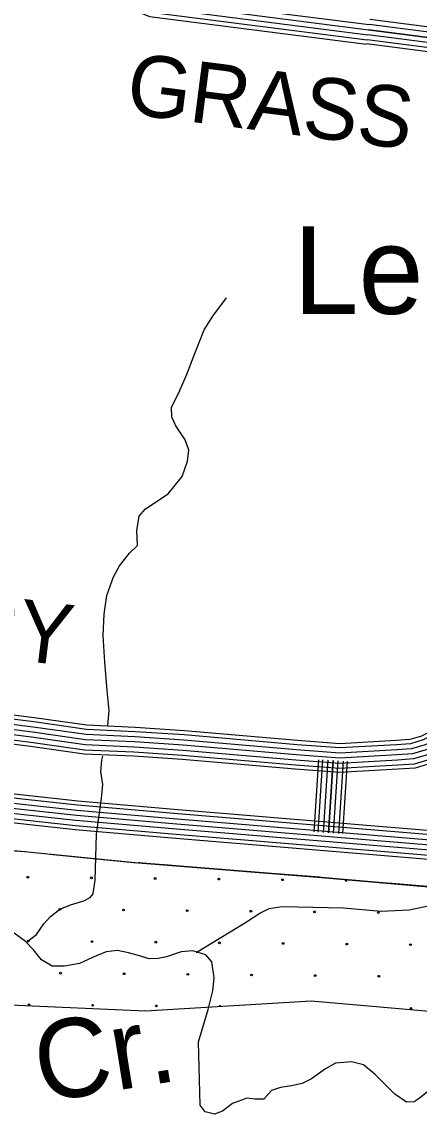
# Model space of a CAD drawing. Extents: x 1788175 to 1969470, y 584502 to 738744.
# Drawn here: x 1839858 to 1842257, y 674647 to 681239 of the extents above; entities that cross this region are included whole.
import ezdxf

# ---------------------------------------------------------------- set-up
doc = ezdxf.new("R2010")
doc.units = 0
for name, color, linetype in [('DESIGN - DRAINAGE - Bridges and Cross Drains Size Text', 7, 'Continuous'), ('DESIGN - EROSION CONTROL - Devices', 7, 'Continuous'), ('DESIGN - ROW - Right-of-Way and Easement Labels', 7, 'Continuous'), ('DESIGN - SCRATCH - User 1', 7, 'Continuous'), ('DESIGN - TRANSPORTATION - Text', 7, 'Continuous'), ('SURVEY - CONTOURS - Index with Text', 7, 'Continuous'), ('SURVEY - TRANSPORTATION - Roads', 7, 'Continuous'), ('SURVEY - VEGETATION - Features with Text', 7, 'Continuous')]:
    doc.layers.add(name, color=color, linetype=linetype)

msp = doc.modelspace()

# ---------------------------------------------------------------- linework, layer by layer
at = {"layer": 'DESIGN - EROSION CONTROL - Devices'}
for centre in [(1839893.4, 676076.8), (1840277.9, 676073.1), (1840662.5, 676069.4), (1841047, 676065.6), (1841431.6, 676061.9), (1840087.5, 675882.7), (1840472.1, 675878.9), (1840856.6, 675875.2), (1841241.2, 675871.5), (1841625.7, 675867.7), (1842010.3, 675864), (1839897.1, 675692.3), (1840281.6, 675688.5), (1840666.2, 675684.8), (1841050.8, 675681.1), (1841435.3, 675677.3), (1841819.9, 675673.6), (1842204.4, 675669.9), (1840091.2, 675498.1), (1840475.8, 675494.4), (1840860.3, 675490.7), (1841244.9, 675486.9), (1841629.4, 675483.2), (1842014, 675479.5), (1839900.8, 675307.7), (1840285.4, 675304), (1840669.9, 675300.3), (1842208.1, 675285.3)]:
    msp.add_circle(centre, 5.28, dxfattribs=at)
for centre, start, end in [((1841816.1, 676058.2), 108.99148, 61.08008), ((1841054.5, 675296.5), 357.64403, 189.12838)]:
    msp.add_arc(centre, 5.28, start, end, dxfattribs=at)
at = {"layer": 'DESIGN - SCRATCH - User 1'}
for points in [[(1839619, 676249.9), (1839873.1, 676232.3), (1840562.4, 676163.7)], [(1840562.4, 676163.7), (1841666.8, 676076), (1842869.2, 675971.5), (1843035.1, 675956.1), (1843451.8, 675929), (1843737.3, 675929), (1843984.3, 675940.6), (1844358.5, 675990.8)], [(1844232.2, 675412.9), (1844051.8, 675193), (1843754.9, 675179.1), (1843427.5, 675179.1), (1842976, 675208.3), (1842801.9, 675224.6), (1841604.7, 675328.5), (1840603.9, 675269.3)], [(1840603.9, 675269.3), (1839785.1, 675304.6), (1839793.9, 674996.2), (1839617.8, 674969.8), (1839019.1, 675031.5), (1838807.8, 674855.2), (1838519.3, 674844.9), (1838260.6, 674867.8), (1838137.5, 674913.9), (1838183.1, 675227)]]:
    msp.add_lwpolyline(points, dxfattribs=at)
at = {"layer": 'DESIGN - TRANSPORTATION - Text'}
for points in [[(1840377.5, 676990.9), (1840385.6, 677083.1), (1840373.5, 677203.4), (1840358.2, 677375.8), (1840348.8, 677536), (1840354.8, 677664), (1840370.6, 677777.9), (1840410.3, 677889.3), (1840447.4, 677956.8), (1840508.5, 678031.9), (1840555.2, 678079.2), (1840552.6, 678169.3), (1840565.9, 678255.2), (1840604.6, 678300.6), (1840741.9, 678390.5), (1840825.4, 678495.2), (1840858.9, 678588.8), (1840865.9, 678654.7), (1840844.9, 678717.1), (1840788.3, 678802.1), (1840763.2, 678852.5), (1840762.2, 678914.6), (1840801.3, 678992), (1840853.1, 679107.3), (1840898.9, 679226.7), (1840959.3, 679379.8), (1841010.6, 679463.1), (1841094.2, 679573.8)], [(1839885, 675685.2), (1839946.6, 675731), (1839989.6, 675796.3), (1840030.3, 675839.7), (1840086.9, 675884.9), (1840151.2, 675909.8), (1840231.5, 675934.6), (1840269.8, 675954), (1840288.1, 675977.7), (1840301.4, 676059.6), (1840307.8, 676337.7), (1840339.2, 676551.4), (1840346.5, 676637.3), (1840333.8, 676713.6), (1840340.9, 676783.5), (1840346.5, 676808.4)], [(1840911, 675623.4), (1841209.1, 675803.6), (1841295.9, 675860.2), (1841352.2, 675887.4), (1841430.3, 675900.1), (1841799.8, 675892.2), (1842027.2, 675872.6), (1842197.1, 675879.9), (1842321.3, 675905.9), (1842397.8, 675942.7), (1842434.4, 675986.2), (1842630, 676186.4)], [(1840924, 675082.7), (1840982.3, 675278.1), (1841011.7, 675391.9), (1841018.7, 675469.8), (1841005.9, 675566.1), (1840968.5, 675608.6), (1840890.9, 675633.5), (1840820.9, 675626.4), (1840730.6, 675597.5), (1840680.5, 675586.1), (1840626.6, 675584.7), (1840554.9, 675605.6), (1840501.1, 675620.3), (1840435.4, 675635.1), (1840367.3, 675625.9), (1840285, 675592.9), (1840206.6, 675555.8), (1840114.6, 675540.9), (1840040.6, 675539.8), (1839977.2, 675578.6), (1839928, 675639.2), (1839880.7, 675689.9), (1839811.3, 675738.7)], [(1842328.9, 674799.3), (1842256.3, 674742.2), (1842226.1, 674720.5), (1842180.1, 674719.1), (1842110.8, 674768), (1841992.4, 674885.5), (1841921.2, 674944.4), (1841849.5, 674963.3), (1841751.5, 674954.5), (1841691.1, 674921.2), (1841606.5, 674860.2), (1841550.2, 674832.8), (1841486.1, 674817.6), (1841420, 674808.4), (1841365.8, 674789), (1841319.2, 674737.5), (1841265.3, 674738.2), (1841217.4, 674742.8), (1841129.1, 674711.8), (1841068.6, 674664.5), (1841020.4, 674647.1), (1840964.7, 674661.8), (1840935.2, 674702.2), (1840924, 675082.7)]]:
    msp.add_lwpolyline(points, dxfattribs=at)
at = {"layer": 'SURVEY - CONTOURS - Index with Text'}
for points in [[(1846534.1, 676635), (1846352.5, 676635), (1846238.5, 676620.8), (1845873.8, 676586.3), (1845636.2, 676551.8), (1845548.2, 676546), (1845443.4, 676528.2), (1845167.8, 676467.4), (1844844.8, 676410.5), (1844348.9, 676328.4), (1844070.1, 676286), (1843940.6, 676275.5), (1843822.6, 676265.1), (1843687, 676265.1), (1843472.1, 676265.1), (1843224.8, 676282.8), (1843014.6, 676297), (1842328.9, 676357.8), (1840777.3, 676486.6), (1840195.7, 676536.6), (1838791.7, 676690.3)], [(1846532.2, 676578.3), (1846356, 676578.3), (1846244.7, 676564.4), (1845880.5, 676530), (1845642.2, 676495.4), (1845554.8, 676489.6), (1845454.2, 676472.5), (1845178.9, 676411.7), (1844854.4, 676354.6), (1844357.8, 676272.4), (1844076.7, 676229.6), (1843945.4, 676219), (1843825.1, 676208.4), (1843687, 676208.4), (1843470.1, 676208.4), (1843220.9, 676226.2), (1843010.2, 676240.5), (1842324.1, 676301.3), (1840772.5, 676430.1), (1840190.2, 676480.1), (1838785.6, 676634)], [(1846533.2, 676609.3), (1846354.1, 676609.3), (1846241.3, 676595.2), (1845876.9, 676560.8), (1845638.9, 676526.2), (1845551.2, 676520.4), (1845448.3, 676503), (1845172.8, 676442.1), (1844849.1, 676385.2), (1844353, 676303), (1844073.1, 676260.5), (1843942.8, 676249.9), (1843823.7, 676239.4), (1843687, 676239.4), (1843471.2, 676239.4), (1843223, 676257.1), (1843012.6, 676271.4), (1842326.7, 676332.2), (1840775.1, 676461), (1840193.2, 676511), (1838788.9, 676664.8)], [(1846530.2, 676516.3), (1846359.9, 676516.3), (1846251.5, 676502.7), (1845887.9, 676468.4), (1845648.7, 676433.7), (1845562.1, 676427.9), (1845466.1, 676411.7), (1845190.9, 676350.9), (1844864.8, 676293.5), (1844367.5, 676211.1), (1844083.8, 676168), (1843950.6, 676157.2), (1843827.8, 676146.4), (1843687, 676146.4), (1843467.8, 676146.4), (1843216.5, 676164.3), (1843005.4, 676178.7), (1842318.8, 676239.5), (1840767.3, 676368.3), (1840184.2, 676418.4), (1838778.9, 676572.3)], [(1846531.2, 676547.3), (1846357.9, 676547.3), (1846248.1, 676533.5), (1845884.2, 676499.2), (1845645.5, 676464.5), (1845558.5, 676458.7), (1845460.2, 676442.1), (1845184.9, 676381.3), (1844859.6, 676324.1), (1844362.7, 676241.8), (1844080.3, 676198.8), (1843948, 676188.1), (1843826.4, 676177.4), (1843687, 676177.4), (1843468.9, 676177.4), (1843218.7, 676195.3), (1843007.8, 676209.6), (1842321.4, 676270.4), (1840769.9, 676399.2), (1840187.2, 676449.3), (1838782.3, 676603.1)], [(1846531.2, 676547.3), (1846357.9, 676547.3), (1846248.1, 676533.5), (1845884.2, 676499.2), (1845645.5, 676464.5), (1845558.5, 676458.7), (1845460.2, 676442.1), (1845184.9, 676381.3), (1844859.6, 676324), (1844362.7, 676241.8), (1844080.3, 676198.8), (1843948, 676188.1), (1843826.4, 676177.4), (1843687, 676177.4), (1843468.9, 676177.4), (1843218.7, 676195.3), (1843007.8, 676209.6), (1842321.4, 676270.4), (1840769.9, 676399.2), (1840187.2, 676449.3), (1838782.3, 676603.1)], [(1846528.4, 676460.6), (1846363.3, 676460.6), (1846257.5, 676447.3), (1845894.5, 676413.1), (1845654.6, 676378.2), (1845568.6, 676372.5), (1845476.8, 676357), (1845201.8, 676296.2), (1844874.2, 676238.6), (1844376.3, 676156.1), (1844090.3, 676112.6), (1843955.3, 676101.7), (1843830.3, 676090.6), (1843687, 676090.6), (1843465.8, 676090.6), (1843212.7, 676108.7), (1843001, 676123.1), (1842314, 676184), (1840762.6, 676312.8), (1840178.8, 676363), (1838773, 676516.9)], [(1846529.2, 676485.3), (1846361.8, 676485.3), (1846254.9, 676471.9), (1845891.6, 676437.6), (1845652, 676402.8), (1845565.7, 676397.1), (1845472, 676381.2), (1845197, 676320.5), (1844870, 676262.9), (1844372.4, 676180.5), (1844087.4, 676137.2), (1843953.2, 676126.3), (1843829.2, 676115.4), (1843687, 676115.4), (1843466.7, 676115.4), (1843214.4, 676133.4), (1843003, 676147.7), (1842316.1, 676208.6), (1840764.7, 676337.4), (1840181.2, 676387.6), (1838775.6, 676541.5)]]:
    msp.add_lwpolyline(points, dxfattribs=at)
at = {"layer": 'SURVEY - TRANSPORTATION - Roads'}
for points in [[(1844246.8, 680947.7), (1844137.1, 681178.6), (1843846.7, 681752.4), (1843754.5, 681949.6), (1843711.3, 681999.1), (1843670.8, 682040.8), (1843614.1, 682076.5), (1843508.5, 682101.9), (1842138.8, 682301.2), (1840817, 682504.2), (1840751.3, 682505), (1840674.7, 682481.8), (1840611.1, 682404.1), (1840586.9, 682273.6), (1840522.4, 681458.4), (1840519.6, 681415.3), (1840523.4, 681313.6), (1840628.6, 681271.9), (1841940.1, 681104.6)], [(1844223.6, 680936.6), (1844114, 681167.3), (1843823.6, 681741.2), (1843732.7, 681935.4), (1843692.4, 681981.7), (1843654.5, 682020.7), (1843603.9, 682052.5), (1843503.6, 682076.6), (1842135, 682275.7), (1840814.8, 682478.5), (1840755, 682479.2), (1840689.7, 682459.4), (1840635.2, 682392.9), (1840612.4, 682270.2), (1840548.1, 681456.6), (1840545.3, 681415), (1840548.5, 681331.3), (1840635.1, 681297), (1841943.4, 681130.1)], [(1844195.5, 680923.3), (1844086.2, 681153.6), (1843795.7, 681727.6), (1843706.5, 681918.3), (1843669.6, 681960.7), (1843634.9, 681996.4), (1843591.7, 682023.5), (1843497.8, 682046.1), (1842130.4, 682245.1), (1840812.3, 682447.5), (1840759.4, 682448.2), (1840707.7, 682432.5), (1840664.2, 682379.4), (1840643.2, 682266.1), (1840579, 681454.4), (1840576.4, 681414.5), (1840578.7, 681352.7), (1840642.9, 681327.3), (1841947.3, 681160.9)], [(1844167.5, 680910), (1844058.4, 681140), (1843767.8, 681714), (1843680.3, 681901.3), (1843646.8, 681939.7), (1843615.2, 681972.1), (1843579.5, 681994.6), (1843491.9, 682015.6), (1842125.8, 682214.4), (1840809.7, 682416.6), (1840763.8, 682417.1), (1840725.7, 682405.6), (1840693.2, 682365.9), (1840673.9, 682262.1), (1840609.9, 681452.1), (1840607.4, 681414.1), (1840608.9, 681374.1), (1840650.7, 681357.5), (1841951.2, 681191.6)], [(1844167.5, 680910), (1844058.4, 681140), (1843767.8, 681714), (1843680.3, 681901.3), (1843646.8, 681939.7), (1843615.2, 681972.1), (1843579.5, 681994.6), (1843491.9, 682015.6), (1842125.8, 682214.4), (1840809.7, 682416.6), (1840763.8, 682417.1), (1840725.7, 682405.6), (1840693.2, 682365.9), (1840673.9, 682262.1), (1840609.9, 681452.1), (1840607.4, 681414.1), (1840608.9, 681374.1), (1840650.7, 681357.5), (1841951.2, 681191.6)], [(1844139.5, 680896.7), (1844030.5, 681126.3), (1843740, 681700.5), (1843654, 681884.2), (1843624, 681918.7), (1843595.6, 681947.8), (1843567.3, 681965.6), (1843486, 681985.2), (1842121.2, 682183.7), (1840807.2, 682385.6), (1840768.2, 682386.1), (1840743.7, 682378.6), (1840722.2, 682352.4), (1840704.7, 682258), (1840640.8, 681449.9), (1840638.5, 681413.7), (1840639.1, 681395.4), (1840658.5, 681387.8), (1841955.1, 681222.4)], [(1845258.1, 680849.7), (1844712.9, 680905.5), (1843538.8, 681049.8), (1841959.1, 681253.1)], [(1845300.2, 680751.9), (1844702.5, 680813.1), (1843527.2, 680957.5), (1841947.3, 681160.9)], [(1845286.2, 680784.5), (1844706, 680843.9), (1843531, 680988.3), (1841951.2, 681191.6)], [(1841951.2, 681191.6), (1843531, 680988.3), (1844706, 680843.9), (1845286.2, 680784.5)], [(1845272.2, 680817.1), (1844709.4, 680874.7), (1843534.9, 681019), (1841955.2, 681222.4)], [(1845325.4, 680693.3), (1844696.3, 680757.7), (1843520.2, 680902.2), (1841940.1, 681105.6)], [(1845314.2, 680719.3), (1844699, 680782.2), (1843523.3, 680926.7), (1841943.3, 681130.1)], [(1842752.5, 677150.9), (1842281.1, 676905.2), (1842205.5, 676882.5), (1842120.9, 676876.5), (1841777.8, 676857.1), (1841519.9, 676876.4), (1840837.5, 676935.5), (1840541.1, 676955.2), (1840248.3, 676968.2), (1839929.4, 677013.8), (1839150.4, 677112), (1838885.6, 677163.7), (1838667.8, 677221.3), (1838273.2, 677373.4), (1836903.4, 678144.5)], [(1842740.6, 677173.7), (1842271.4, 676929.1), (1842200.8, 676908), (1842119.2, 676902.2), (1841778, 676882.8), (1841522, 676902), (1840839.5, 676961.1), (1840542.5, 676980.9), (1840250.7, 676993.9), (1839932.8, 677039.3), (1839154.5, 677137.4), (1838891.3, 677188.7), (1838675.8, 677245.8), (1838284.2, 677396.7), (1836916, 678166.9)], [(1842795.5, 677068.4), (1842316.3, 676818.6), (1842222.3, 676790.5), (1842126.8, 676783.7), (1841777, 676763.9), (1841512.4, 676783.7), (1840830.4, 676842.7), (1840535.9, 676862.4), (1840239.6, 676875.5), (1839917, 676921.6), (1839135.7, 677020.1), (1838864.8, 677073), (1838639.1, 677132.7), (1838233.5, 677289), (1836857.8, 678063.5)], [(1842781.2, 677095.9), (1842304.6, 676847.5), (1842216.7, 676821.2), (1842124.9, 676814.6), (1841777.2, 676794.9), (1841514.9, 676814.6), (1840832.8, 676873.6), (1840537.6, 676893.3), (1840242.5, 676906.4), (1839921.1, 676952.3), (1839140.6, 677050.7), (1838871.7, 677103.2), (1838648.7, 677162.2), (1838246.7, 677317.1), (1836873, 678090.5)], [(1842781.2, 677095.9), (1842304.6, 676847.5), (1842216.7, 676821.2), (1842124.9, 676814.6), (1841777.2, 676794.9), (1841514.9, 676814.6), (1840832.8, 676873.6), (1840537.6, 676893.3), (1840242.5, 676906.4), (1839921.1, 676952.3), (1839140.6, 677050.7), (1838871.7, 677103.2), (1838648.7, 677162.2), (1838246.7, 677317.1), (1836873, 678090.5)], [(1842766.8, 677123.4), (1842292.9, 676876.3), (1842211.1, 676851.8), (1842122.9, 676845.6), (1841777.5, 676826), (1841517.4, 676845.5), (1840835.1, 676904.5), (1840539.3, 676924.3), (1840245.4, 676937.3), (1839925.2, 676983.1), (1839145.5, 677081.4), (1838878.6, 677133.4), (1838658.3, 677191.8), (1838260, 677345.2), (1836888.2, 678117.5)], [(1842821.3, 677019), (1842337.3, 676766.7), (1842232.4, 676735.4), (1842130.4, 676728.1), (1841776.4, 676708), (1841507.9, 676728.2), (1840826.1, 676787.2), (1840532.8, 676806.7), (1840234.4, 676820), (1839909.5, 676866.4), (1839126.9, 676965.1), (1838852.3, 677018.6), (1838621.9, 677079.6), (1838209.7, 677238.5), (1836830.5, 678014.9)], [(1842809.8, 677040.9), (1842328, 676789.8), (1842227.9, 676759.8), (1842128.8, 676752.7), (1841776.7, 676732.8), (1841509.9, 676752.8), (1840828, 676811.8), (1840534.2, 676831.4), (1840236.7, 676844.6), (1839912.8, 676890.9), (1839130.8, 676989.5), (1838857.8, 677042.7), (1838629.6, 677103.2), (1838220.2, 677260.9), (1836842.6, 678036.5)], [(1841623.2, 676351.3), (1841651.2, 676786.1)], [(1841647.8, 676349.7), (1841675.8, 676784.5)], [(1841678.8, 676347.7), (1841706.8, 676782.5)], [(1841709.7, 676345.7), (1841737.7, 676780.5)], [(1841737.7, 676780.5), (1841709.7, 676345.7)], [(1841709.7, 676345.7), (1841737.7, 676780.5)], [(1841740.6, 676343.7), (1841768.7, 676778.5)], [(1841771.6, 676341.7), (1841799.6, 676776.5)], [(1841797.2, 676340.1), (1841825.3, 676774.9)]]:
    msp.add_lwpolyline(points, dxfattribs=at)
at = {"layer": 'SURVEY - VEGETATION - Features with Text'}
for points in [[(1839614.4, 676256.2), (1839873.1, 676232.3), (1840562.4, 676163.7)], [(1839614.4, 676256.2), (1839873.1, 676232.3), (1839877.3, 676231.8)], [(1840026.5, 676217), (1840289.2, 676190.9)], [(1840289.2, 676190.9), (1840551.9, 676164.8)], [(1844358.5, 675990.8), (1843984.3, 675940.6), (1843737.3, 675929), (1843451.8, 675929), (1843035.1, 675956.1), (1842869.2, 675971.5), (1841666.8, 676076), (1840562.4, 676163.7)], [(1840567.8, 676163.3), (1840562.4, 676163.7)], [(1840980.5, 676130.5), (1840717.3, 676151.4)], [(1841243.6, 676109.6), (1840980.5, 676130.5)], [(1841656.3, 676076.8), (1841393.1, 676097.7)], [(1841919.3, 676054), (1841666.8, 676076), (1841656.3, 676076.8)], [(1842331.8, 676018.2), (1842068.8, 676041.1)]]:
    msp.add_lwpolyline(points, dxfattribs=at)

# ---------------------------------------------------------------- texts
at = {"layer": 'DESIGN - DRAINAGE - Bridges and Cross Drains Size Text'}
msp.add_text('Cr.', height=475, rotation=9.18549, dxfattribs=at).set_placement((1839974, 674715.9))
at = {"layer": 'DESIGN - ROW - Right-of-Way and Easement Labels'}
for s, rotation, p in [('GRASS', 352.72908, (1840477.6, 680687.1)), ('ORY', 352.81503, (1839078.8, 677483.2))]:
    msp.add_text(s, height=370, rotation=rotation, dxfattribs=at).set_placement(p)
at = {"layer": 'SURVEY - VEGETATION - Features with Text'}
msp.add_text('Leevil le', height=528, dxfattribs=at).set_placement((1841498.1, 679476.8))

doc.saveas('drawing.dxf')
